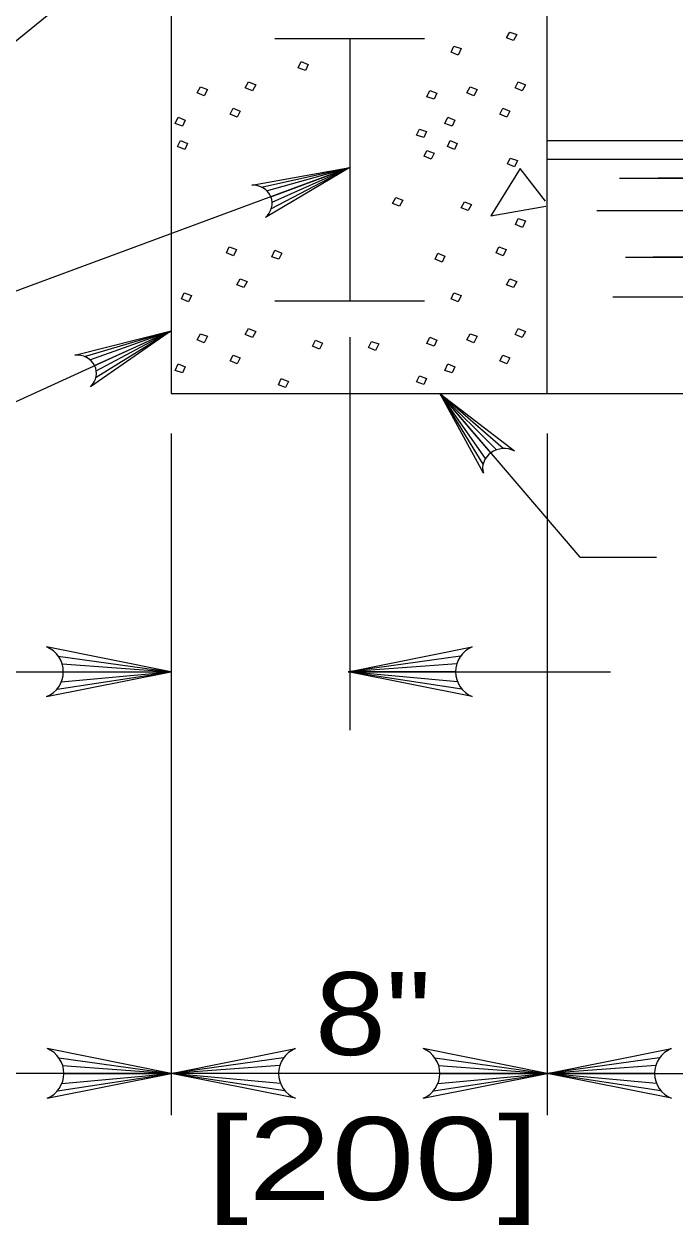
# Model space of a CAD drawing. Extents: x -1431.2 to -1397.2, y -1045.1 to -1001.1.
# Drawn here: x -1423.385 to -1422.139, y -1041.697 to -1039.396 of the extents above; entities that cross this region are included whole.
import ezdxf
from ezdxf.enums import TextEntityAlignment as Align

# ---------------------------------------------------------------- set-up
doc = ezdxf.new("R2010")
doc.units = 0
doc.header["$LTSCALE"] = 0.064
doc.layers.add('1', color=7, linetype='Continuous', lineweight=13)

msp = doc.modelspace()

# ---------------------------------------------------------------- linework, layer by layer
at = {"layer": '1', "lineweight": 25}
for p, q in [((-1422.38333, -1040.10408), (-1422.38333, -1038.96642)), ((-1423.1035, -1039.093), (-1423.1035, -1040.10408)), ((-1422.905, -1039.42333), (-1422.61842, -1039.42333)), ((-1422.76167, -1039.42333), (-1422.76167, -1039.92642)), ((-1422.38333, -1039.61925), (-1421.35642, -1039.61925)), ((-1422.905, -1039.92642), (-1422.61842, -1039.92642))]:
    msp.add_line(p, q, dxfattribs=at)
at = {"layer": '1'}
for p, q in [((-1422.76167, -1039.57183), (-1422.76167, -1039.92642)), ((-1422.38333, -1039.65508), (-1421.61217, -1039.65508)), ((-1422.93067, -1039.70825), (-1422.76167, -1039.67058)), ((-1422.92075, -1039.71517), (-1422.76167, -1039.67058)), ((-1422.91267, -1039.72683), (-1422.76167, -1039.67058)), ((-1422.91142, -1039.74917), (-1422.76167, -1039.67058)), ((-1422.91008, -1039.73742), (-1422.76167, -1039.67058)), ((-1422.38675, -1039.735), (-1422.43508, -1039.67292)), ((-1422.24483, -1039.69092), (-1421.98408, -1039.69092)), ((-1421.79125, -1039.69092), (-1422.1705, -1039.69092)), ((-1422.28817, -1039.75308), (-1421.52967, -1039.75308)), ((-1422.23358, -1039.84283), (-1421.99242, -1039.84283)), ((-1421.75308, -1039.84283), (-1422.18017, -1039.84283)), ((-1421.37983, -1039.91908), (-1422.25742, -1039.91908)), ((-1423.26942, -1040.033), (-1423.1035, -1039.98375)), ((-1423.25908, -1040.03925), (-1423.1035, -1039.98375)), ((-1423.25025, -1040.05025), (-1423.1035, -1039.98375)), ((-1423.24742, -1040.07242), (-1423.1035, -1039.98375)), ((-1423.24692, -1040.06067), (-1423.1035, -1039.98375)), ((-1422.76167, -1039.99608), (-1422.76167, -1040.749)), ((-1422.49108, -1040.21758), (-1422.58833, -1040.10425)), ((-1422.50133, -1040.22833), (-1422.58833, -1040.10425)), ((-1422.50617, -1040.23908), (-1422.58833, -1040.10425)), ((-1422.4805, -1040.212), (-1422.58833, -1040.10425)), ((-1422.46775, -1040.20933), (-1422.58833, -1040.10425)), ((-1422.58833, -1040.10425), (-1422.32058, -1040.41733)), ((-1423.1035, -1040.18058), (-1423.1035, -1041.48717)), ((-1422.38333, -1040.18058), (-1422.38333, -1041.48717)), ((-1423.1035, -1040.25708), (-1423.1035, -1040.32108)), ((-1422.32058, -1040.41733), (-1422.17383, -1040.41733)), ((-1423.31975, -1040.607), (-1423.1045, -1040.63708)), ((-1422.54933, -1040.607), (-1422.7645, -1040.63708)), ((-1423.31242, -1040.62192), (-1423.1045, -1040.63708)), ((-1422.55658, -1040.62192), (-1422.7645, -1040.63708)), ((-1424.02625, -1040.63708), (-1423.1045, -1040.63708)), ((-1423.32225, -1040.67042), (-1423.1045, -1040.63708)), ((-1423.314, -1040.65642), (-1423.1045, -1040.63708)), ((-1423.31025, -1040.63708), (-1423.1045, -1040.63708)), ((-1423.10458, -1040.63708), (-1423.1045, -1040.63708)), ((-1422.7645, -1040.63708), (-1422.26183, -1040.63708)), ((-1422.55883, -1040.63708), (-1422.7645, -1040.63708)), ((-1422.555, -1040.65642), (-1422.7645, -1040.63708)), ((-1422.54675, -1040.67042), (-1422.7645, -1040.63708)), ((-1423.31867, -1041.37675), (-1423.1035, -1041.40692)), ((-1423.31142, -1041.39167), (-1423.1035, -1041.40692)), ((-1422.88825, -1041.37675), (-1423.1035, -1041.40692)), ((-1422.8955, -1041.39167), (-1423.1035, -1041.40692)), ((-1422.5985, -1041.37675), (-1422.38333, -1041.40692)), ((-1422.59125, -1041.39167), (-1422.38333, -1041.40692)), ((-1422.16808, -1041.37675), (-1422.38333, -1041.40692)), ((-1422.17542, -1041.39167), (-1422.38333, -1041.40692)), ((-1423.1035, -1041.40692), (-1423.9725, -1041.40692)), ((-1423.32125, -1041.44017), (-1423.1035, -1041.40692)), ((-1423.313, -1041.42625), (-1423.1035, -1041.40692)), ((-1423.30917, -1041.40692), (-1423.1035, -1041.40692)), ((-1422.38333, -1041.40692), (-1423.1035, -1041.40692)), ((-1422.89775, -1041.40692), (-1423.1035, -1041.40692)), ((-1422.89392, -1041.42625), (-1423.1035, -1041.40692)), ((-1422.88567, -1041.44017), (-1423.1035, -1041.40692)), ((-1422.60108, -1041.44017), (-1422.38333, -1041.40692)), ((-1422.59283, -1041.42625), (-1422.38333, -1041.40692)), ((-1422.589, -1041.40692), (-1422.38333, -1041.40692)), ((-1422.17758, -1041.40692), (-1422.38333, -1041.40692)), ((-1422.17383, -1041.42625), (-1422.38333, -1041.40692)), ((-1422.16558, -1041.44017), (-1422.38333, -1041.40692))]:
    msp.add_line(p, q, dxfattribs=at)
for points in [[(-1422.9885, -1039.093), (-1423.93175, -1039.859), (-1424.2065, -1039.859)], [(-1422.76167, -1039.67058), (-1424.21225, -1040.20775), (-1426.82292, -1040.20775)], [(-1422.94917, -1039.70442), (-1422.76167, -1039.67058), (-1422.92317, -1039.76675)], [(-1422.43508, -1039.67292), (-1422.49125, -1039.7635), (-1422.38583, -1039.74492)], [(-1423.1035, -1039.98375), (-1424.58483, -1040.66075), (-1424.85158, -1040.66075)], [(-1423.28825, -1040.03042), (-1423.1035, -1039.98375), (-1423.25792, -1040.09083)], [(-1422.50567, -1040.2565), (-1422.58833, -1040.10425), (-1422.44617, -1040.21392)], [(-1423.34225, -1040.68467), (-1423.1045, -1040.63708), (-1423.34225, -1040.58958)], [(-1422.52683, -1040.68467), (-1422.7645, -1040.63708), (-1422.52683, -1040.58958)], [(-1423.34117, -1041.45442), (-1423.1035, -1041.40692), (-1423.34117, -1041.35933)], [(-1422.86575, -1041.45442), (-1423.1035, -1041.40692), (-1422.86575, -1041.35933)], [(-1422.62108, -1041.45442), (-1422.38333, -1041.40692), (-1422.62108, -1041.35933)], [(-1422.14558, -1041.45442), (-1422.38333, -1041.40692), (-1422.14558, -1041.35933)], [(-1422.38333, -1041.40692), (-1421.92633, -1041.40692), (-1421.35642, -1041.40692)]]:
    msp.add_lwpolyline(points, dxfattribs=at)
for points in [[(-1422.455, -1039.41117), (-1422.44142, -1039.41608), (-1422.44775, -1039.4275), (-1422.46133, -1039.42258)], [(-1422.56192, -1039.43808), (-1422.54833, -1039.443), (-1422.55375, -1039.45525), (-1422.56733, -1039.4495)], [(-1422.85467, -1039.46742), (-1422.841, -1039.47317), (-1422.8465, -1039.48458), (-1422.86008, -1039.47967)], [(-1422.95517, -1039.50658), (-1422.94158, -1039.51233), (-1422.948, -1039.52375), (-1422.96158, -1039.518)], [(-1422.43867, -1039.50658), (-1422.42508, -1039.51233), (-1422.43142, -1039.52375), (-1422.445, -1039.518)], [(-1423.04767, -1039.51642), (-1423.03408, -1039.52125), (-1423.04042, -1039.5335), (-1423.054, -1039.52783)], [(-1422.60817, -1039.52292), (-1422.59458, -1039.52858), (-1422.6, -1039.54), (-1422.61358, -1039.53517)], [(-1422.53108, -1039.51642), (-1422.5175, -1039.52125), (-1422.52383, -1039.5335), (-1422.53742, -1039.52783)], [(-1423.09025, -1039.57425), (-1423.07667, -1039.58), (-1423.08208, -1039.59142), (-1423.09567, -1039.5865)], [(-1422.98508, -1039.55717), (-1422.9715, -1039.56283), (-1422.97692, -1039.57425), (-1422.99058, -1039.56858)], [(-1422.57367, -1039.57425), (-1422.56008, -1039.58), (-1422.56558, -1039.59142), (-1422.57917, -1039.5865)], [(-1422.46858, -1039.55717), (-1422.455, -1039.56283), (-1422.46042, -1039.57425), (-1422.474, -1039.56858)], [(-1422.62808, -1039.59708), (-1422.6145, -1039.602), (-1422.61992, -1039.61342), (-1422.6335, -1039.6085)], [(-1423.08567, -1039.61917), (-1423.07208, -1039.62483), (-1423.0775, -1039.63625), (-1423.09117, -1039.63058)], [(-1422.56917, -1039.61917), (-1422.55558, -1039.62483), (-1422.561, -1039.63625), (-1422.57458, -1039.63058)], [(-1422.61358, -1039.63792), (-1422.6, -1039.64358), (-1422.60542, -1039.655), (-1422.619, -1039.64933)], [(-1422.45408, -1039.65258), (-1422.4405, -1039.65742), (-1422.44592, -1039.66967), (-1422.4595, -1039.664)], [(-1422.67342, -1039.72842), (-1422.65975, -1039.73333), (-1422.66617, -1039.74475), (-1422.67975, -1039.73983)], [(-1422.542, -1039.73658), (-1422.52842, -1039.74142), (-1422.53475, -1039.75292), (-1422.54833, -1039.748)], [(-1422.43867, -1039.76833), (-1422.42508, -1039.77325), (-1422.4305, -1039.7855), (-1422.44408, -1039.77975)], [(-1422.99233, -1039.823), (-1422.97875, -1039.82792), (-1422.98417, -1039.84017), (-1422.99783, -1039.83442)], [(-1422.90533, -1039.8295), (-1422.89175, -1039.83525), (-1422.89725, -1039.84667), (-1422.91083, -1039.84175)], [(-1422.47583, -1039.823), (-1422.46225, -1039.82792), (-1422.46767, -1039.84017), (-1422.48125, -1039.83442)], [(-1422.59275, -1039.83525), (-1422.57917, -1039.84092), (-1422.58458, -1039.85233), (-1422.59817, -1039.84667)], [(-1422.9715, -1039.88417), (-1422.95792, -1039.88908), (-1422.96425, -1039.9005), (-1422.97783, -1039.89558)], [(-1422.455, -1039.88417), (-1422.44142, -1039.88908), (-1422.44775, -1039.9005), (-1422.46133, -1039.89558)], [(-1423.07842, -1039.91108), (-1423.06483, -1039.916), (-1423.07033, -1039.92817), (-1423.08392, -1039.9225)], [(-1422.56192, -1039.91108), (-1422.54833, -1039.916), (-1422.55375, -1039.92817), (-1422.56733, -1039.9225)], [(-1423.04767, -1039.98933), (-1423.03408, -1039.99425), (-1423.04042, -1040.0065), (-1423.054, -1040.00075)], [(-1422.95517, -1039.97958), (-1422.94158, -1039.98525), (-1422.948, -1039.99667), (-1422.96158, -1039.991)], [(-1422.53108, -1039.98933), (-1422.5175, -1039.99425), (-1422.52383, -1040.0065), (-1422.53742, -1040.00075)], [(-1422.43867, -1039.97958), (-1422.42508, -1039.98525), (-1422.43142, -1039.99667), (-1422.445, -1039.991)], [(-1422.82742, -1040.00158), (-1422.81383, -1040.00733), (-1422.81925, -1040.01875), (-1422.83292, -1040.013)], [(-1422.71958, -1040.004), (-1422.706, -1040.00892), (-1422.71233, -1040.02117), (-1422.72592, -1040.0155)], [(-1422.60817, -1039.99592), (-1422.59458, -1040.00158), (-1422.6, -1040.013), (-1422.61358, -1040.00808)], [(-1422.98508, -1040.03017), (-1422.9715, -1040.03583), (-1422.97692, -1040.04725), (-1422.99058, -1040.04158)], [(-1422.46858, -1040.03017), (-1422.455, -1040.03583), (-1422.46042, -1040.04725), (-1422.474, -1040.04158)], [(-1423.09025, -1040.04725), (-1423.07667, -1040.053), (-1423.08208, -1040.06442), (-1423.09567, -1040.0595)], [(-1422.57367, -1040.04725), (-1422.56008, -1040.053), (-1422.56558, -1040.06442), (-1422.57917, -1040.0595)], [(-1422.89267, -1040.075), (-1422.87908, -1040.08067), (-1422.8845, -1040.09208), (-1422.89808, -1040.08725)], [(-1422.62808, -1040.07008), (-1422.6145, -1040.075), (-1422.61992, -1040.08642), (-1422.6335, -1040.0815)]]:
    msp.add_lwpolyline(points, close=True, dxfattribs=at)
at = {"layer": '1', "lineweight": 25}
msp.add_lwpolyline([(-1423.1035, -1040.10408), (-1422.38333, -1040.10408), (-1420.649, -1040.10408)], dxfattribs=at)
at = {"layer": '1'}
for centre, start, end in [((-1423.36144, -1040.63705), 292.08605, 67.91218), ((-1422.5076, -1040.63705), 112.08782, 247.91395), ((-1423.36039, -1041.40683), 292.08605, 67.91218), ((-1422.84652, -1041.40683), 112.08782, 247.91395), ((-1422.64025, -1041.40683), 292.08605, 67.91218), ((-1422.12638, -1041.40683), 112.08782, 247.91395)]:
    msp.add_arc(centre, 0.05131, start, end, dxfattribs=at)
for centre, major_axis, start_param, end_param in [((-1422.95035, -1039.74082), (0.0397, 0.00715), 5.2950757, 7.6656889), ((-1423.28684, -1040.06682), (0.03911, 0.00988), 5.2950757, 7.6656889), ((-1422.46681, -1040.24583), (0.03973, 0.00696), 0.8762993, 3.2469125)]:
    msp.add_ellipse(centre, major_axis=major_axis, ratio=0.899905, start_param=start_param, end_param=end_param, dxfattribs=at)

# ---------------------------------------------------------------- texts
for s, width, p in [('8"', 1.15, (-1422.717, -1041.37158)), ('[200]', 1.35, (-1422.717, -1041.64942))]:
    msp.add_text(s, height=0.1588, dxfattribs=dict(at, width=width)).set_placement(p, align=Align.CENTER)

doc.saveas('drawing.dxf')
